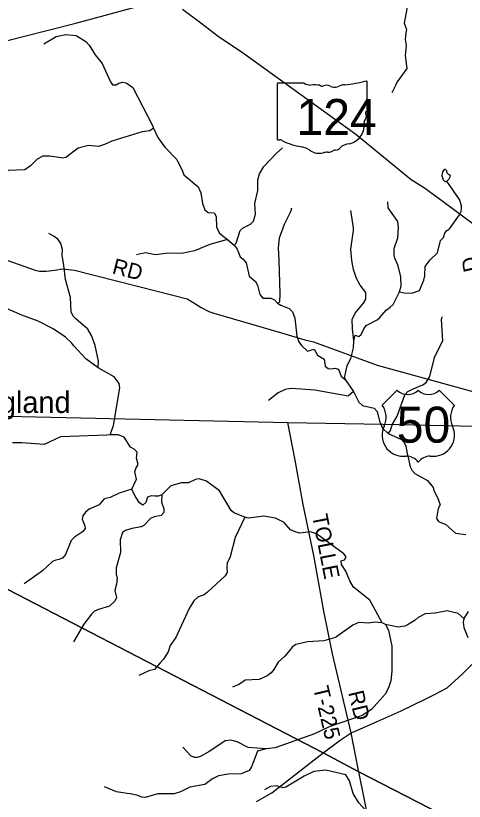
# Model space of a CAD drawing. Extents: x 1525783 to 1900577, y 218250 to 627376.
# Drawn here: x 1636103 to 1644767, y 433381 to 448562 of the extents above; entities that cross this region are included whole.
import ezdxf

# ---------------------------------------------------------------- set-up
doc = ezdxf.new("R2010")
doc.units = 0
for name, color, linetype in [('GM_X_Minor_Lake', 7, 'Continuous'), ('GM_X_Minor_River', 7, 'Continuous'), ('GM_X_State_Location', 7, 'Continuous'), ('GM_X_State_Route', 7, 'Continuous'), ('GM_X_State_Shield', 7, 'Continuous'), ('GM_X_Township', 7, 'Continuous'), ('GM_X_Township_Road', 7, 'Continuous'), ('GM_X_Township_Road_Text', 7, 'Continuous'), ('GM_X_Unincorporated_Text', 7, 'Continuous'), ('GM_X_US_Location', 7, 'Continuous'), ('GM_X_US_Route', 7, 'Continuous'), ('GM_X_US_Shield', 7, 'Continuous')]:
    doc.layers.add(name, color=color, linetype=linetype)

msp = doc.modelspace()

# ---------------------------------------------------------------- linework, layer by layer
at = {"layer": 'GM_X_Minor_Lake'}
for points in [[(1644432, 445362), (1644475, 445407), (1644495, 445449), (1644500, 445477), (1644478, 445483), (1644460, 445491), (1644442, 445510), (1644431, 445542), (1644427, 445566), (1644413, 445584), (1644397, 445596), (1644371, 445579), (1644347, 445543), (1644338, 445513), (1644334, 445467), (1644343, 445427), (1644359, 445393), (1644378, 445368)], [(1644378, 445368), (1644415, 445353), (1644432, 445362)]]:
    msp.add_lwpolyline(points, dxfattribs=at)
at = {"layer": 'GM_X_Minor_River'}
for points in [[(1643663, 448730), (1643605, 448418), (1643649, 448298), (1643636, 448228), (1643625, 448110), (1643647, 447981), (1643627, 447795), (1643657, 447541), (1643472, 447287), (1643437, 447211), (1643368, 447070)], [(1636646, 448021), (1636882, 448158), (1637072, 448198), (1637270, 448177), (1637460, 448064), (1637519, 447992), (1637636, 447806), (1637774, 447636), (1637931, 447283), (1637974, 447225), (1638040, 447224), (1638093, 447257), (1638165, 447276), (1638239, 447267), (1638365, 447177), (1638745, 446442), (1638767, 446391), (1638848, 446210), (1638984, 446024), (1639214, 445785), (1639321, 445557), (1639348, 445488), (1639629, 445254), (1639677, 445136), (1639711, 444933), (1639757, 444808), (1639820, 444759), (1639936, 444752), (1639975, 444679), (1639980, 444485), (1640033, 444368), (1640171, 444252)], [(1638767, 446391), (1638690, 446338), (1638548, 446316), (1637958, 446139), (1637820, 446075), (1637703, 446035), (1637506, 446055), (1637307, 446002), (1637069, 445821), (1637011, 445811), (1636892, 445827), (1636758, 445849), (1636626, 445849), (1636514, 445792), (1636386, 445663), (1636277, 445581), (1635962, 445573), (1635895, 445552), (1635762, 445459)], [(1640319, 444128), (1640358, 444164), (1640435, 444413), (1640496, 444466), (1640636, 444532), (1640697, 444594), (1640733, 444727), (1640723, 444932), (1640776, 445181), (1640777, 445392), (1640809, 445507), (1640894, 445650), (1641133, 445902), (1641255, 446010)], [(1643518, 443223), (1643631, 443199), (1643771, 443206), (1643904, 443252), (1643984, 443453), (1644003, 443535), (1644011, 443713), (1644109, 443846), (1644251, 443982), (1644308, 444218), (1644362, 444277), (1644389, 444357), (1644426, 444408), (1644484, 444446), (1644677, 444712), (1644706, 444777), (1644713, 444835), (1644712, 444891), (1644675, 445012), (1644432, 445362)], [(1642631, 442279), (1642658, 442387), (1642728, 442366), (1642778, 442402), (1642825, 442511), (1642872, 442573), (1643083, 442686), (1643136, 442727), (1643256, 442874), (1643328, 442923), (1643391, 442984), (1643518, 443223), (1643545, 443345), (1643541, 443515), (1643492, 443726), (1643428, 443879), (1643413, 443931), (1643415, 444061), (1643481, 444267), (1643496, 444467), (1643481, 444583), (1643297, 444852), (1643289, 444968)], [(1641156, 443010), (1641204, 443035), (1641212, 443183), (1641189, 443842), (1641178, 444073), (1641196, 444269), (1641293, 444532), (1641414, 444780), (1641437, 444848)], [(1642465, 441535), (1642460, 441587), (1642505, 441804), (1642574, 441938), (1642627, 442147), (1642631, 442279), (1642606, 442510), (1642604, 442692), (1642656, 442814), (1642822, 443010), (1642867, 443087), (1642864, 443215), (1642754, 443357), (1642684, 443486), (1642624, 443657), (1642593, 443832), (1642578, 444050), (1642626, 444414), (1642627, 444466), (1642575, 444795)], [(1637692, 441755), (1637700, 441885), (1637636, 442189), (1637564, 442380), (1637494, 442505), (1637263, 442702), (1637214, 442753), (1637175, 442838), (1637162, 443118), (1637065, 443462), (1637032, 443733), (1636999, 443937), (1637006, 444041), (1636974, 444160), (1636921, 444235), (1636848, 444296), (1636741, 444351)], [(1640192, 444235), (1639852, 444140), (1639555, 444020), (1639309, 443969), (1639047, 443972), (1638801, 443942), (1638608, 443978), (1638435, 443944)], [(1640171, 444252), (1640192, 444235)], [(1640192, 444235), (1640319, 444128), (1640380, 444053), (1640438, 443902), (1640498, 443855), (1640553, 443788), (1640609, 443529), (1640732, 443424), (1640771, 443355), (1640816, 443174), (1640877, 443103), (1641027, 443103), (1641099, 443072), (1641156, 443010), (1641225, 442969), (1641384, 442902), (1641451, 442841), (1641496, 442717), (1641535, 442368), (1641572, 442257), (1641623, 442188), (1641739, 442081), (1641866, 442115), (1641930, 442004), (1642063, 441922), (1642079, 441792), (1642138, 441745), (1642202, 441736), (1642268, 441753), (1642334, 441731), (1642365, 441662), (1642390, 441594), (1642465, 441535), (1642624, 441302), (1642729, 441093), (1642800, 441030), (1643023, 440981), (1643087, 440916), (1643128, 440727), (1643190, 440592), (1643299, 440490), (1643553, 440373), (1643604, 440316), (1643637, 440246), (1643665, 440101), (1643675, 440049), (1643722, 439846), (1643751, 439782), (1643810, 439715), (1644058, 439583), (1644168, 439444), (1644176, 439386), (1644248, 439250), (1644300, 439110), (1644259, 439040), (1644233, 438848), (1644270, 438790), (1644409, 438730), (1644599, 438565), (1644798, 438538)], [(1637927, 440461), (1637990, 440642), (1638111, 441373), (1638098, 441454), (1638002, 441585), (1637692, 441755), (1637455, 441933), (1637226, 442182), (1637189, 442237), (1637063, 442348), (1636825, 442512), (1636539, 442660), (1636221, 442776), (1635770, 442966), (1635629, 443008), (1635566, 443045), (1635530, 443107), (1635465, 443156), (1635272, 443237), (1635195, 443270), (1634995, 443439)], [(1643299, 440490), (1643333, 440532), (1643379, 440670), (1643469, 440825), (1643620, 441235), (1643675, 441298), (1643781, 441353), (1643964, 441429), (1644033, 441472), (1644102, 441587), (1644189, 441956), (1644283, 442141), (1644351, 442279), (1644328, 442684), (1644340, 442741)], [(1642624, 441302), (1642525, 441209), (1641881, 441328), (1641624, 441343), (1641424, 441360), (1641304, 441336), (1641174, 441275), (1640988, 441123)], [(1644761, 436913), (1644647, 437013), (1644434, 437062), (1644205, 437019), (1644011, 437003), (1643875, 436933), (1643820, 436881), (1643685, 436795), (1643617, 436764), (1643487, 436746), (1643246, 436795), (1643180, 436830), (1643014, 437138), (1642942, 437269), (1642628, 437518), (1642555, 437641), (1642480, 437830), (1642394, 437957), (1642388, 438027), (1642455, 438047), (1642485, 438106), (1642438, 438163), (1641914, 438550), (1641796, 438590), (1641590, 438565), (1641517, 438580), (1641407, 438629), (1641289, 438767), (1641121, 438853), (1640897, 438888), (1640601, 438854), (1640530, 438873), (1640315, 438958), (1640264, 438998), (1640039, 439382), (1639785, 439567), (1639644, 439613), (1639578, 439600), (1639441, 439536), (1639304, 439534), (1639101, 439480), (1638925, 439304), (1638857, 439279), (1638789, 439278), (1638719, 439283), (1638649, 439258), (1638616, 439154), (1638555, 439105), (1638492, 439148), (1638407, 439277), (1638347, 439414), (1638438, 439603), (1638402, 439746), (1638422, 439814), (1638467, 439889), (1638435, 440010), (1638446, 440126), (1638391, 440188), (1638320, 440223), (1638198, 440417), (1638083, 440461), (1637927, 440461), (1637865, 440458), (1636966, 440427), (1636651, 440273), (1636218, 440311), (1636042, 440309)], [(1638347, 439414), (1638101, 439333), (1637928, 439249), (1637810, 439223), (1637714, 439110), (1637523, 439024), (1637451, 438967), (1637396, 438896), (1637389, 438830), (1637439, 438707), (1637443, 438653), (1637394, 438586), (1637239, 438484), (1637176, 438422), (1637067, 438153), (1637004, 438080), (1636934, 438051), (1636878, 438038), (1636811, 438015), (1636617, 437835), (1636265, 437583)], [(1638925, 439304), (1638919, 439164), (1638964, 439032), (1638961, 438961), (1638910, 438904), (1638774, 438878), (1638706, 438843), (1638576, 438710), (1638524, 438683), (1638344, 438655), (1638223, 438617), (1638163, 438574), (1638117, 438436), (1638124, 438192), (1638042, 437894), (1638043, 437766), (1638060, 437700), (1638052, 437574), (1638019, 437454), (1638047, 437318), (1638020, 437248), (1637915, 437153), (1637702, 437088), (1637626, 437053), (1637569, 437000), (1637421, 436807), (1637219, 436460)], [(1640530, 438873), (1640341, 438479), (1640246, 438108), (1640189, 437984), (1640180, 437908), (1640184, 437802), (1640148, 437737), (1639806, 437421), (1639743, 437373), (1639619, 437327), (1639546, 437252), (1639454, 437107), (1639198, 436548), (1639088, 436395), (1639046, 436269), (1638955, 436130), (1638894, 436055), (1638786, 435928), (1638674, 435902), (1638479, 435812)], [(1644839, 437046), (1644761, 436913)], [(1644761, 436913), (1644746, 436843), (1644757, 436741), (1644833, 436546)], [(1643246, 436795), (1643300, 436690), (1643368, 436379), (1643368, 435894), (1643350, 435708), (1643304, 435575), (1643237, 435452), (1642975, 435155), (1642794, 435041), (1642158, 434817), (1641871, 434683), (1641116, 434414), (1640940, 434397), (1640595, 434423), (1640382, 434528), (1640257, 434560), (1640147, 434547), (1639913, 434386), (1639841, 434345), (1639672, 434245), (1639610, 434226), (1639556, 434229), (1639486, 434258), (1639331, 434430)], [(1643180, 436830), (1643037, 436844), (1642916, 436825), (1642729, 436836), (1642614, 436783), (1642280, 436545), (1642051, 436482), (1641739, 436462), (1641511, 436409), (1641444, 436360), (1641406, 436307), (1641300, 436186), (1641169, 436067), (1641087, 435928), (1641037, 435865), (1640960, 435806), (1640803, 435736), (1640537, 435719), (1640465, 435668), (1640415, 435637), (1640288, 435588)], [(1640940, 434397), (1640772, 434351), (1640656, 434046), (1640609, 433979), (1640457, 433914), (1640203, 433904), (1640021, 433872), (1639904, 433814), (1639757, 433709), (1639464, 433655), (1639284, 433561), (1639161, 433525), (1638850, 433527), (1638603, 433456), (1638537, 433459), (1638462, 433496), (1638322, 433528), (1638256, 433531), (1638051, 433562), (1637819, 433663)], [(1643016, 432880), (1643027, 432952), (1642859, 433208), (1642731, 433352), (1642623, 433534), (1642550, 433777), (1642476, 433894), (1642095, 433985), (1641859, 433954), (1641672, 433864), (1641322, 433653), (1641270, 433644), (1641147, 433681), (1641021, 433665), (1640906, 433602)]]:
    msp.add_lwpolyline(points, dxfattribs=at)
at = {"layer": 'GM_X_State_Route'}
for points in [[(1639324, 448689), (1639681, 448421), (1640014, 448167), (1640499, 447835), (1642674, 446273), (1643740, 445398), (1643998, 445237), (1644356, 444973), (1644956, 444524)], [(1640755, 433378), (1641048, 433544), (1642041, 434318), (1642369, 434565), (1642584, 434704), (1642649, 434732), (1643084, 434922), (1643549, 435132), (1644013, 435353), (1644190, 435443), (1644439, 435574), (1644727, 435838), (1645108, 436212)]]:
    msp.add_lwpolyline(points, dxfattribs=at)
at = {"layer": 'GM_X_State_Shield'}
for p, q in [((1641150, 447238), (1641150, 446182)), ((1641677, 447256), (1641167, 447256)), ((1642890, 446730), (1642890, 447283)), ((1642890, 446730), (1642890, 446730))]:
    msp.add_line(p, q, dxfattribs=at)
for centre, major_axis, start_param, end_param in [((1641170, 447241), (20.2, 0), 1.712693, 3.28349), ((1641798, 447379), (196, 0), 4.042523, 4.731795), ((1641863, 446663), (702, 0), 1.404758, 1.657858), ((1642022, 447246), (56.4, 0), 3.836095, 5.185415), ((1642105, 447124), (117, 0), 0.950623, 2.079405), ((1642506, 446934), (371, 0), 1.699011, 2.107814), ((1642270, 448697), (1845, 0), 4.814394, 5.042369), ((1642871, 447285), (19.4, 0), 6.141152, 7.989035), ((1642257, 447291), (141, 0), 4.081561, 5.145723), ((1642886, 446689), (30, 0), 1.883978, 3.671073), ((1642695, 446619), (180, 0), 5.934695, 6.695948), ((1642870, 446728), (20.7, 0), 5.05454, 6.418171), ((1642374, 446428), (462, 0), 5.101752, 6.440018), ((1642960, 446499), (131, 0), 2.387724, 3.262537), ((1641170, 446179), (20.3, 0), 3.00124, 4.508301), ((1641173, 446287), (155, 0), 4.665946, 4.897461), ((1641205, 446121), (56, 0), 0.519207, 1.627899), ((1641912, 447070), (1333, 0), 4.195997, 4.488961), ((1641514, 445707), (417, 0), 0.823519, 1.323587), ((1642248, 446079), (149, 0), 4.937069, 5.64225), ((1642568, 445885), (253, 0), 1.647645, 2.488434), ((1641965, 446115), (265, 0), 4.026481, 4.996735), ((1642118, 445750), (217, 0), 1.495662, 1.94098), ((1642137, 446036), (141, 0), 4.691044, 5.507374), ((1642265, 445934), (39.7, 0), 1.147584, 2.315152)]:
    msp.add_ellipse(centre, major_axis=major_axis, ratio=0.8, start_param=start_param, end_param=end_param, dxfattribs=at)
at = {"layer": 'GM_X_Township'}
for points in [[(1646572, 431971), (1642730, 433950), (1642041, 434318), (1633605, 438688)], [(1633605, 438688), (1642041, 434318), (1642730, 433950), (1646572, 431971)]]:
    msp.add_lwpolyline(points, dxfattribs=at)
at = {"layer": 'GM_X_Township_Road'}
for points in [[(1633703, 447497), (1635437, 447951), (1636245, 448159), (1637266, 448417), (1639044, 448906)], [(1634299, 444246), (1635290, 444066), (1636481, 443645), (1636563, 443625), (1636691, 443627), (1636860, 443647), (1637003, 443669), (1637237, 443646), (1638832, 443240), (1639415, 443089), (1639540, 443015), (1639687, 442921), (1639830, 442847), (1639927, 442816), (1641236, 442434), (1641684, 442299), (1641855, 442260), (1643086, 441808), (1645050, 441269), (1645109, 441250)], [(1642718, 434009), (1642584, 434704), (1642220, 436233), (1642057, 437054), (1641859, 438128), (1641657, 439115), (1641499, 439976), (1641356, 440703)], [(1644381, 430241), (1644337, 430316), (1643784, 430783), (1643659, 430919), (1643499, 431208), (1643274, 431582), (1643168, 431759), (1643121, 432009), (1642730, 433950), (1642718, 434009)]]:
    msp.add_lwpolyline(points, dxfattribs=at)
at = {"layer": 'GM_X_US_Route'}
for points in [[(1622451, 440961), (1623894, 440943), (1626649, 440908), (1627244, 440901), (1629564, 440875), (1629984, 440871), (1631031, 440859), (1633920, 440868), (1641356, 440703), (1643192, 440667)], [(1643192, 440667), (1644994, 440632)]]:
    msp.add_lwpolyline(points, dxfattribs=at)
at = {"layer": 'GM_X_US_Shield'}
for p, q in [((1643472, 441326), (1643182, 441036)), ((1644574, 441036), (1644284, 441326)), ((1643588, 440050), (1643646, 440050)), ((1644110, 440050), (1644168, 440050))]:
    msp.add_line(p, q, dxfattribs=at)
for centre, radius, start, end in [((1643675, 441533), 290, 225.573, 314.427), ((1644081, 441533), 290, 225.573, 314.427), ((1642850, 440803), 406, 334.5471, 35.0009), ((1644907, 440803), 406, 144.9991, 205.4529), ((1643584, 440456), 406, 154.8319, 270.6383), ((1644173, 440456), 406, 269.3617, 25.1681), ((1643646, 439760), 290, 36.8699, 90), ((1644110, 439760), 290, 90, 143.1301)]:
    msp.add_arc(centre, radius, start, end, dxfattribs=at)

# ---------------------------------------------------------------- texts
at = {"layer": 'GM_X_State_Location'}
for s in ['s', 'r']:
    msp.add_text(s, height=1, dxfattribs=at).set_placement((1642001, 446640))
msp.add_text('124', height=1, rotation=0, dxfattribs=at).set_placement((1641648, 446567))
at = {"layer": 'GM_X_State_Shield'}
msp.add_text('124', height=696.1, dxfattribs=at).set_placement((1641525, 446256))
at = {"layer": 'GM_X_Township_Road_Text'}
for s, rotation, p in [('D', 103.3135, (1645058, 443651)), ('RD', 345.4836, (1637949, 443587)), ('TOLLE', 281.0979, (1641825, 438902)), ('T-225', 283.3537, (1641845, 435573)), ('RD', 283.5536, (1642523, 435483))]:
    msp.add_text(s, height=300, rotation=rotation, dxfattribs=at).set_placement(p)
at = {"layer": 'GM_X_Unincorporated_Text'}
msp.add_text('Hoagland', height=417, rotation=0, dxfattribs=at).set_placement((1634775, 440885))
at = {"layer": 'GM_X_US_Location'}
for s in ['0', '/']:
    msp.add_text(s, height=1, dxfattribs=at).set_placement((1643878, 440654))
msp.add_text('50', height=1, rotation=0, dxfattribs=at).set_placement((1643672, 440447))
at = {"layer": 'GM_X_US_Shield'}
msp.add_text('50', height=696.1, dxfattribs=at).set_placement((1643462, 440311))

doc.saveas('drawing.dxf')
